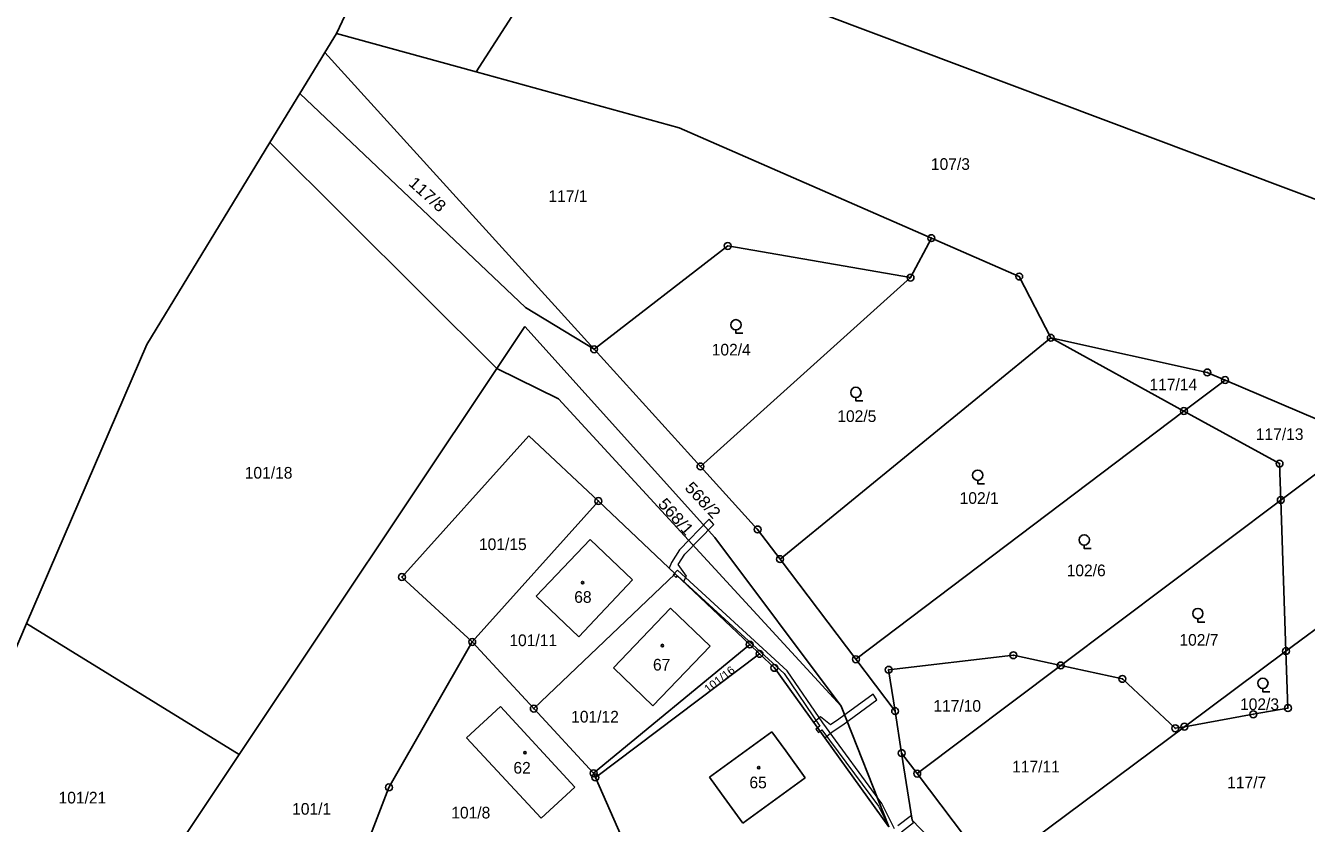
# Model space of a CAD drawing. Extents: x -664548 to -662415, y -1069720 to -1068208.
# Drawn here: x -664002.1 to -663815.4, y -1068781.7 to -1068665.4 of the extents above; entities that cross this region are included whole.
import ezdxf
from ezdxf.enums import TextEntityAlignment as Align

# ---------------------------------------------------------------- set-up
doc = ezdxf.new("R2010")
doc.units = 0
doc.header["$LTSCALE"] = 0.68
for name, color, linetype, lineweight in [('1', 7, 'Continuous', 25), ('13', 7, 'Continuous', 13), ('3', 7, 'Continuous', 25), ('5', 7, 'Continuous', 25), ('8', 7, 'Continuous', 25)]:
    doc.layers.add(name, color=color, linetype=linetype, lineweight=lineweight)
doc.layers.add('2', color=7, linetype='Continuous')

msp = doc.modelspace()

# ---------------------------------------------------------------- linework, layer by layer
at = {"layer": '1'}
for p, q in [((-663940.82, -1068632.85), (-663956.81, -1068666.54)), ((-663936.42, -1068672.14), (-663922.26, -1068650.01)), ((-663798.21, -1068696.66), (-663922.26, -1068650.01)), ((-663958.5, -1068669.31), (-663956.81, -1068666.54)), ((-663936.42, -1068672.14), (-663956.81, -1068666.54)), ((-663959.09, -1068670.28), (-663958.5, -1068669.31)), ((-663919.24, -1068712.57), (-663958.5, -1068669.31)), ((-663962.15, -1068675.29), (-663959.09, -1068670.28)), ((-663906.82, -1068680.27), (-663936.42, -1068672.14)), ((-663966.5, -1068682.41), (-663962.15, -1068675.29)), ((-663929.23, -1068706.46), (-663962.15, -1068675.29)), ((-663870.07, -1068696.36), (-663906.82, -1068680.27)), ((-663966.5, -1068682.41), (-663984.48, -1068711.88)), ((-663933.41, -1068715.36), (-663966.5, -1068682.41)), ((-663873.11, -1068702.12), (-663870.07, -1068696.36)), ((-663857.27, -1068701.96), (-663870.07, -1068696.36)), ((-663899.76, -1068697.51), (-663919.24, -1068712.57)), ((-663899.76, -1068697.51), (-663873.11, -1068702.12)), ((-663903.74, -1068729.65), (-663873.11, -1068702.12)), ((-663852.66, -1068710.89), (-663857.27, -1068701.96)), ((-663929.23, -1068706.46), (-663919.24, -1068712.57)), ((-663929.34, -1068709.23), (-663933.41, -1068715.36)), ((-663901.64, -1068740.01), (-663929.34, -1068709.23)), ((-663984.48, -1068711.88), (-664001.98, -1068752.55)), ((-663892.13, -1068743.16), (-663852.66, -1068710.89)), ((-663852.66, -1068710.89), (-663829.84, -1068715.95)), ((-663833.24, -1068721.57), (-663852.66, -1068710.89)), ((-663903.74, -1068729.65), (-663919.24, -1068712.57)), ((-663970.99, -1068771.67), (-663933.41, -1068715.36)), ((-663933.41, -1068715.36), (-663924.43, -1068719.81)), ((-663829.84, -1068715.95), (-663827.26, -1068717.05)), ((-663827.26, -1068717.05), (-663833.24, -1068721.57)), ((-663827.26, -1068717.05), (-663807.23, -1068725.61)), ((-663924.43, -1068719.81), (-663883.22, -1068764.61)), ((-663833.24, -1068721.57), (-663881.07, -1068757.77)), ((-663819.31, -1068729.24), (-663833.24, -1068721.57)), ((-663928.76, -1068725.2), (-663947.26, -1068745.77)), ((-663918.62, -1068734.69), (-663928.76, -1068725.2)), ((-663807.23, -1068725.61), (-663819.13, -1068734.55)), ((-663895.4, -1068738.84), (-663903.74, -1068729.65)), ((-663819.31, -1068729.24), (-663819.13, -1068734.55)), ((-663937.02, -1068755.24), (-663918.62, -1068734.69)), ((-663907.41, -1068745.32), (-663918.62, -1068734.69)), ((-663819.13, -1068734.55), (-663851.21, -1068758.67)), ((-663819.13, -1068734.55), (-663818.37, -1068756.58)), ((-663927.68, -1068748.58), (-663919.81, -1068740.3)), ((-663919.81, -1068740.3), (-663913.64, -1068746.17)), ((-663883.22, -1068764.61), (-663901.64, -1068740.01)), ((-663892.13, -1068743.16), (-663895.4, -1068738.84)), ((-663881.07, -1068757.77), (-663892.13, -1068743.16)), ((-663947.26, -1068745.77), (-663937.02, -1068755.24)), ((-663907.41, -1068745.32), (-663928.04, -1068764.96)), ((-663907.41, -1068745.32), (-663896.56, -1068755.61)), ((-663802.07, -1068744.46), (-663818.37, -1068756.58)), ((-663913.64, -1068746.17), (-663921.48, -1068754.47)), ((-663921.48, -1068754.47), (-663927.68, -1068748.58)), ((-663908.1, -1068750.33), (-663916.43, -1068759.03)), ((-663902.32, -1068755.85), (-663908.1, -1068750.33)), ((-664001.98, -1068752.55), (-664010.86, -1068773.2)), ((-663970.99, -1068771.67), (-664001.98, -1068752.55)), ((-663949.15, -1068776.44), (-663937.02, -1068755.24)), ((-663937.02, -1068755.24), (-663928.04, -1068764.96)), ((-663896.56, -1068755.61), (-663919.32, -1068774.39)), ((-663919.06, -1068774.98), (-663895.12, -1068756.98)), ((-663910.66, -1068764.55), (-663902.32, -1068755.85)), ((-663896.56, -1068755.61), (-663895.12, -1068756.98)), ((-663895.12, -1068756.98), (-663892.96, -1068759.02)), ((-663818.37, -1068756.58), (-663833.18, -1068767.59)), ((-663818.37, -1068756.58), (-663818.08, -1068764.88)), ((-663875.36, -1068765.32), (-663881.07, -1068757.77)), ((-663876.3, -1068759.3), (-663858.11, -1068757.17)), ((-663851.21, -1068758.67), (-663872.14, -1068774.44)), ((-663851.21, -1068758.67), (-663858.11, -1068757.17)), ((-663842.22, -1068760.62), (-663851.21, -1068758.67)), ((-663916.43, -1068759.03), (-663910.66, -1068764.55)), ((-663876.25, -1068782.21), (-663892.96, -1068759.02)), ((-663876.3, -1068759.3), (-663875.36, -1068765.32)), ((-663842.22, -1068760.62), (-663834.51, -1068767.83)), ((-663937.83, -1068769.2), (-663932.89, -1068764.66)), ((-663932.89, -1068764.66), (-663922.06, -1068776.4)), ((-663928.04, -1068764.96), (-663919.32, -1068774.39)), ((-663883.22, -1068764.61), (-663876.25, -1068782.21)), ((-663874.41, -1068771.45), (-663875.36, -1068765.32)), ((-663823.14, -1068765.79), (-663833.18, -1068767.59)), ((-663823.14, -1068765.79), (-663818.08, -1068764.88)), ((-663902.43, -1068774.95), (-663893.35, -1068768.33)), ((-663893.35, -1068768.33), (-663891.31, -1068771.12)), ((-663833.18, -1068767.59), (-663861.38, -1068788.6)), ((-663833.18, -1068767.59), (-663834.51, -1068767.83)), ((-663926.94, -1068780.94), (-663937.83, -1068769.2)), ((-663980.88, -1068786.48), (-663970.99, -1068771.67)), ((-663888.45, -1068775.05), (-663891.31, -1068771.12)), ((-663872.89, -1068781.23), (-663874.41, -1068771.45)), ((-663872.14, -1068774.44), (-663874.41, -1068771.45)), ((-663919.32, -1068774.39), (-663919.06, -1068774.98)), ((-663912.63, -1068789.6), (-663919.06, -1068774.98)), ((-663900.68, -1068777.36), (-663902.43, -1068774.95)), ((-663897.54, -1068781.67), (-663888.45, -1068775.05)), ((-663861.38, -1068788.6), (-663872.14, -1068774.44)), ((-663954.1, -1068789.23), (-663949.15, -1068776.44)), ((-663922.06, -1068776.4), (-663926.94, -1068780.94)), ((-663900.68, -1068777.36), (-663897.54, -1068781.67)), ((-663872.89, -1068781.23), (-663862.1, -1068792.34))]:
    msp.add_line(p, q, dxfattribs=at)
at = {"layer": '13'}
for points in [[(-663907.95, -1068743.65), (-663908.31, -1068744.47), (-663907.41, -1068745.32), (-663906.22, -1068746.45), (-663905.77, -1068745.65), (-663906.97, -1068743.97), (-663906, -1068742.43), (-663901.81, -1068738.1), (-663902.49, -1068737.36), (-663906.78, -1068741.82)], [(-663886.24, -1068766.15), (-663887.21, -1068766.99), (-663886.53, -1068767.94), (-663885.61, -1068769.22), (-663884.52, -1068768.35), (-663882.97, -1068767.32), (-663878.01, -1068763.66), (-663878.58, -1068762.85), (-663883.56, -1068766.5), (-663884.79, -1068767.33)]]:
    msp.add_lwpolyline(points, close=True, dxfattribs=at)
for points in [[(-663875.44, -1068782.47), (-663877.3, -1068778.81), (-663885.91, -1068767.04), (-663891.08, -1068759.46), (-663907.11, -1068744.77), (-663907.73, -1068745.43), (-663907.3, -1068745.84), (-663907.09, -1068745.62), (-663891.53, -1068759.86), (-663886.32, -1068767.51), (-663886.9, -1068767.94), (-663886.55, -1068768.43), (-663886.04, -1068768.05), (-663877.8, -1068779.16), (-663876.25, -1068782.21)], [(-663874.43, -1068782.9), (-663872.66, -1068781.56), (-663872.89, -1068781.23), (-663872.99, -1068780.56), (-663874.98, -1068782.06)]]:
    msp.add_lwpolyline(points, dxfattribs=at)
at = {"layer": '3'}
for points in [[(-663898.56, -1068709.742), (-663898.56, -1068710.24), (-663897.559, -1068710.24)], [(-663881.08, -1068719.602), (-663881.08, -1068720.1), (-663880.079, -1068720.1)], [(-663863.32, -1068731.682), (-663863.32, -1068732.18), (-663862.319, -1068732.18)], [(-663847.78, -1068741.122), (-663847.78, -1068741.62), (-663846.779, -1068741.62)], [(-663831.22, -1068751.852), (-663831.22, -1068752.35), (-663830.219, -1068752.35)], [(-663821.74, -1068762.022), (-663821.74, -1068762.52), (-663820.739, -1068762.52)]]:
    msp.add_lwpolyline(points, dxfattribs=at)
for centre in [(-663898.5593, -1068708.9909), (-663881.0793, -1068718.8509), (-663863.3193, -1068730.9309), (-663847.7793, -1068740.3709), (-663831.2193, -1068751.1009), (-663821.7393, -1068761.2709)]:
    msp.add_circle(centre, 0.75, dxfattribs=at)
at = {"layer": '5'}
for centre in [(-663920.9268, -1068746.5892), (-663909.2868, -1068755.7592), (-663929.3268, -1068771.3892), (-663895.2368, -1068773.5692)]:
    msp.add_circle(centre, 0.175, dxfattribs=at)
at = {"layer": '8'}
for centre, radius in [((-663899.7599, -1068697.5099), 0.5), ((-663870.0699, -1068696.3599), 0.5), ((-663870.0699, -1068696.3599), 0.0303), ((-663899.7599, -1068697.5099), 0.0303), ((-663873.1099, -1068702.1199), 0.5), ((-663873.1099, -1068702.1199), 0.0303), ((-663857.2699, -1068701.9599), 0.5), ((-663857.2699, -1068701.9599), 0.0303), ((-663852.6599, -1068710.8899), 0.5), ((-663919.2399, -1068712.5699), 0.5), ((-663852.6599, -1068710.8899), 0.0303), ((-663919.2399, -1068712.5699), 0.0303), ((-663829.8399, -1068715.9499), 0.5), ((-663829.8399, -1068715.9499), 0.0303), ((-663827.2599, -1068717.0499), 0.5), ((-663827.2599, -1068717.0499), 0.0303), ((-663833.2399, -1068721.5699), 0.5), ((-663833.2399, -1068721.5699), 0.0303), ((-663819.3099, -1068729.2399), 0.5), ((-663903.7399, -1068729.6499), 0.5), ((-663903.7399, -1068729.6499), 0.0303), ((-663819.3099, -1068729.2399), 0.0303), ((-663918.62, -1068734.6899), 0.5), ((-663918.62, -1068734.6899), 0.0303), ((-663819.1299, -1068734.5499), 0.5), ((-663819.1299, -1068734.5499), 0.0303), ((-663895.4, -1068738.8399), 0.5), ((-663895.4, -1068738.8399), 0.0303), ((-663892.1299, -1068743.1599), 0.5), ((-663892.1299, -1068743.1599), 0.0303), ((-663947.26, -1068745.7699), 0.5), ((-663947.26, -1068745.7699), 0.0303), ((-663937.02, -1068755.2399), 0.5), ((-663937.02, -1068755.2399), 0.0303), ((-663896.56, -1068755.6099), 0.5), ((-663896.56, -1068755.6099), 0.0303), ((-663895.12, -1068756.9799), 0.5), ((-663895.12, -1068756.9799), 0.0303), ((-663858.1099, -1068757.1699), 0.5), ((-663818.3699, -1068756.5799), 0.5), ((-663818.3699, -1068756.5799), 0.0303), ((-663892.96, -1068759.0199), 0.5), ((-663892.96, -1068759.0199), 0.0303), ((-663881.0699, -1068757.7699), 0.5), ((-663881.0699, -1068757.7699), 0.0303), ((-663876.2999, -1068759.2999), 0.5), ((-663858.1099, -1068757.1699), 0.0303), ((-663851.2099, -1068758.6699), 0.5), ((-663851.2099, -1068758.6699), 0.0303), ((-663876.2999, -1068759.2999), 0.0303), ((-663842.2199, -1068760.6199), 0.5), ((-663842.2199, -1068760.6199), 0.0303), ((-663928.04, -1068764.9599), 0.5), ((-663818.0799, -1068764.8799), 0.5), ((-663928.04, -1068764.9599), 0.0303), ((-663875.3599, -1068765.3199), 0.5), ((-663875.3599, -1068765.3199), 0.0303), ((-663823.1399, -1068765.7899), 0.5), ((-663823.1399, -1068765.7899), 0.0303), ((-663818.0799, -1068764.8799), 0.0303), ((-663834.5099, -1068767.8299), 0.5), ((-663834.5099, -1068767.8299), 0.0303), ((-663833.1799, -1068767.5899), 0.5), ((-663833.1799, -1068767.5899), 0.0303), ((-663874.41, -1068771.4499), 0.5), ((-663874.41, -1068771.4499), 0.0303), ((-663919.32, -1068774.3899), 0.5), ((-663872.1399, -1068774.4399), 0.5), ((-663919.06, -1068774.9799), 0.5), ((-663919.32, -1068774.3899), 0.0303), ((-663919.06, -1068774.9799), 0.0303), ((-663872.1399, -1068774.4399), 0.0303), ((-663949.15, -1068776.4399), 0.5), ((-663949.15, -1068776.4399), 0.0303)]:
    msp.add_circle(centre, radius, dxfattribs=at)

# ---------------------------------------------------------------- texts
at = {"layer": '2'}
for s, p in [('107/3', (-663870.14, -1068686.415)), ('117/1', (-663925.9, -1068691.084)), ('101/18', (-663970.18, -1068731.425)), ('102/1', (-663865.95, -1068735.104)), ('101/15', (-663936.03, -1068741.844)), ('68', (-663922.14, -1068749.535)), ('101/11', (-663931.6, -1068755.844)), ('67', (-663910.66, -1068759.405)), ('102/3', (-663825.07, -1068765.165)), ('101/12', (-663922.59, -1068766.985)), ('62', (-663931.01, -1068774.435)), ('65', (-663896.6, -1068776.574)), ('117/7', (-663826.94, -1068776.574)), ('101/1', (-663963.27, -1068780.425)), ('101/8', (-663940.07, -1068780.975))]:
    msp.add_text(s, height=1.7, dxfattribs=at).set_placement(p)
at = {"layer": '2', "width": 1.1}
for s, height, rotation, p in [('117/8', 1.7, 318, (-663946.434, -1068688.515)), ('568/1', 1.7, 312, (-663910.035, -1068735.204)), ('101/16', 1.14, 38, (-663902.654, -1068762.704))]:
    msp.add_text(s, height=height, rotation=rotation, dxfattribs=at).set_placement(p)
at = {"layer": '2'}
for s, p in [('102/4', (-663899.25, -1068713.475)), ('117/14', (-663834.8, -1068718.564)), ('102/5', (-663880.94, -1068723.165)), ('117/13', (-663819.29, -1068725.795)), ('102/6', (-663847.5, -1068745.655)), ('102/7', (-663831.06, -1068755.785)), ('117/10', (-663866.31, -1068765.415)), ('117/11', (-663854.82, -1068774.265)), ('101/21', (-663993.85, -1068778.785))]:
    msp.add_text(s, height=1.7, dxfattribs=at).set_placement(p, align=Align.CENTER)
at = {"layer": '2', "width": 1.1}
msp.add_text('568/2', height=1.7, rotation=313, dxfattribs=at).set_placement((-663904.0056, -1068735.1443), align=Align.CENTER)

doc.saveas('drawing.dxf')
